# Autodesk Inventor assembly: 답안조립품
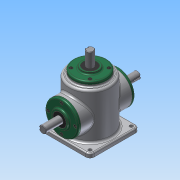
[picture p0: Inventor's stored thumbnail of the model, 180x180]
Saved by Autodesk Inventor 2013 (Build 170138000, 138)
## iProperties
Created: 2015-10
Part Number: 답안조립품
Document SubType Name: Assembly
Designer: Administrator
Author: Administrator
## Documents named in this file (14)
- C:\Users\Administrator\Desktop\451008V1012\답안조립품.iam
- C:\Users\Administrator\Desktop\451008V1012\본체.ipt
- C:\Users\Administrator\Desktop\451008V1012\M4.ipt
- C:\Users\Administrator\Desktop\451008V1012\메인 베벨기어.ipt
- C:\Users\Administrator\Desktop\451008V1012\메인 축.ipt
- 메인 축.ipt
- C:\Users\Administrator\Desktop\451008V1012\베어링 6203.ipt
- C:\Users\Administrator\Desktop\451008V1012\서브 베벨기어.ipt
- C:\Users\Administrator\Desktop\451008V1012\서브 축.ipt
- 서브 축.ipt
- C:\Users\Administrator\Desktop\451008V1012\오일실.ipt
- C:\Users\Administrator\Desktop\451008V1012\커버.ipt
- C:\Users\Administrator\Desktop\451008V1012\키 4x4.ipt
- C:\Users\Administrator\Desktop\451008V1012\키 5x5.ipt
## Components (12 placed, 1 different names)
1. M4:3
2. M4:4
3. M4:5
4. M4:6
5. M4:1
6. M4:7
7. M4:8
8. M4:9
9. M4:2
10. M4:10
11. M4:11
12. M4:12
